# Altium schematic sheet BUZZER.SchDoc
size A4; Revision: V1.2; SheetNumber: 7; SheetTotal: 10
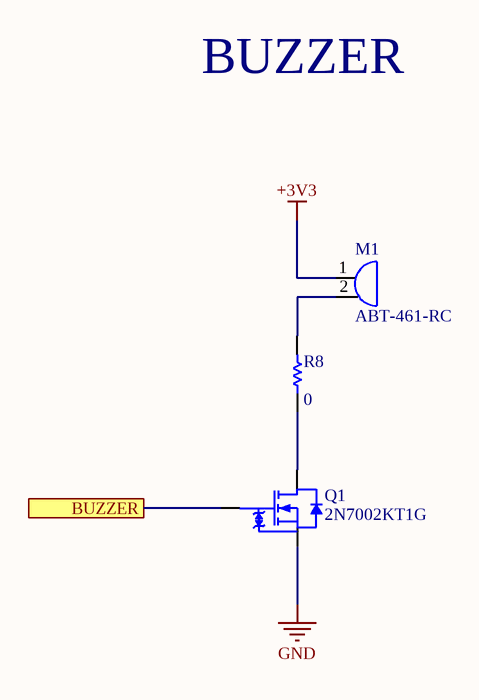
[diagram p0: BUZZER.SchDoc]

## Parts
M1  ABT-461-RC  [ABT-461-RC-Footprint-1]
Q1  2N7002KT1G  [SOT23]
R8  value 0  [RES-0402]  (hidden comment: CRCW04020000Z0EDC)

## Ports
BUZZER

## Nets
+3V3: M1.1
GND: Q1.2(S)
BUZZER: Q1.1(G) ; port BUZZER
NetM1_2: M1.2 R8.2
NetQ1_3: Q1.3(D) R8.1

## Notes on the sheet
- BUZZER

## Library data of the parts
M1 = S0011-A.4: BUZZER 2 V, 4 V, 100 mA, 85 dB; Manufacturer: Multicomp Pro; Code Arduino: S0011
Q1 = T0004-A.3: MOSFET N-CH 60V 300mA SOT23; Manufacturer: On Semiconductor; Code Arduino: A5393; Device Type: Mosfet N-CH SMD
R8 = R0000-A.11: RES CHIP 0402 0R 1/16W; Manufacturer: Vishay; Code Arduino: 0039; Power: 63mW; Tolerance: J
